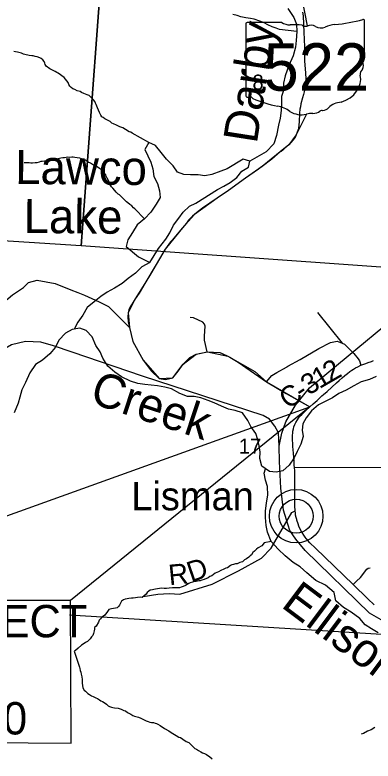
# Model space of a CAD drawing. Extents: x 0 to 82.7, y -0.2 to 22.
# Drawn here: x 6.593 to 7.589, y 16.831 to 18.905 of the extents above; entities that cross this region are included whole.
import ezdxf

# ---------------------------------------------------------------- set-up
doc = ezdxf.new("R2010")
doc.units = 0
for name, color, linetype in [('Default', 7, 'Continuous'), ('GM_X_County_Road', 7, 'Continuous'), ('GM_X_County_Road_Text', 7, 'Continuous'), ('GM_X_Minor_Lake', 7, 'Continuous'), ('GM_X_Minor_Lake_Text', 7, 'Continuous'), ('GM_X_Minor_River', 7, 'Continuous'), ('GM_X_Minor_River_Text', 7, 'Continuous'), ('GM_X_Rail_Line', 7, 'Continuous'), ('GM_X_Section', 7, 'Continuous'), ('GM_X_Section_Text', 7, 'Continuous'), ('GM_X_State_Location', 7, 'Continuous'), ('GM_X_State_Route', 7, 'Continuous'), ('GM_X_State_Shield', 7, 'Continuous'), ('GM_X_Township_Road', 7, 'Continuous'), ('GM_X_Unincorporated', 7, 'Continuous'), ('GM_X_Unincorporated_Location', 7, 'Continuous'), ('GM_X_Unincorporated_Text', 7, 'Continuous'), ('SH_Data', 7, 'Continuous'), ('SH_Text', 7, 'Continuous')]:
    doc.layers.add(name, color=color, linetype=linetype)

msp = doc.modelspace()

# ---------------------------------------------------------------- linework, layer by layer
at = {"layer": 'Default'}
msp.add_lwpolyline([(5.916, 17.2773), (5.9127, 16.8876), (6.7496, 16.8806), (6.7482, 17.2774)], dxfattribs=at)
at = {"layer": 'GM_X_County_Road'}
for points in [[(6.2254, 17.8971), (6.228, 17.8985), (6.3326, 17.9376), (6.3894, 17.9596), (6.4281, 17.9767), (6.4614, 17.9881), (6.4811, 17.9953), (6.491, 17.9995), (6.5004, 18.0158), (6.5137, 18.0488), (6.5251, 18.0704), (6.544, 18.0924), (6.5868, 18.1273), (6.6168, 18.1478), (6.6312, 18.1611), (6.655, 18.1676), (6.7047, 18.1592), (6.7488, 18.1415), (6.7681, 18.1337)], [(6.7681, 18.1337), (6.7865, 18.1263), (6.8275, 18.1081), (6.8532, 18.0944), (6.9114, 18.036)], [(7.3477, 17.9266), (7.3486, 17.9271), (7.3522, 17.9291), (7.3858, 17.9477), (7.438, 17.9776), (7.4703, 17.995), (7.4889, 17.9987), (7.503, 17.9926), (7.5088, 17.99), (7.5349, 17.9639), (7.5474, 17.949), (7.5511, 17.944), (7.5543, 17.9314)], [(7.2923, 17.8858), (7.3074, 17.903), (7.3211, 17.9117), (7.3477, 17.9266)], [(6.9494, 17.2887), (6.9909, 17.2954), (7.0224, 17.2973), (7.0515, 17.295), (7.1414, 17.3231), (7.2149, 17.36), (7.2785, 17.3953), (7.3058, 17.4233), (7.363, 17.522), (7.3722, 17.5271)]]:
    msp.add_lwpolyline(points, dxfattribs=at)
at = {"layer": 'GM_X_Minor_Lake'}
for points in [[(7.0958, 18.3823), (7.1566, 18.4199), (7.1741, 18.429), (7.1916, 18.4395), (7.2098, 18.4539), (7.2243, 18.4712), (7.2425, 18.4818), (7.2464, 18.4992), (7.2275, 18.5046), (7.1834, 18.4775), (7.1652, 18.4708), (7.1402, 18.4618), (7.1212, 18.4581), (7.1023, 18.4612), (7.0811, 18.4613), (7.0629, 18.4621), (7.0455, 18.4683), (7.0327, 18.4858), (7.0146, 18.5041), (6.9996, 18.5232), (6.9838, 18.5422), (6.9656, 18.5506), (6.9542, 18.5317), (6.9624, 18.5135), (6.9707, 18.496), (6.9766, 18.4777), (6.9796, 18.4564), (6.9893, 18.4367), (6.9953, 18.4161), (6.9974, 18.3979), (6.986, 18.379), (6.9707, 18.357), (6.9532, 18.3389), (6.9334, 18.3215), (6.9204, 18.3003), (6.9067, 18.2799), (6.9021, 18.2617), (6.9369, 18.2329), (6.9685, 18.2174)], [(6.9685, 18.2174), (6.98, 18.2363), (6.9922, 18.256), (7.0128, 18.2824), (7.0242, 18.2999), (7.0342, 18.3211), (7.0487, 18.34), (7.0609, 18.3574), (7.0784, 18.374), (7.0958, 18.3823)]]:
    msp.add_lwpolyline(points, dxfattribs=at)
at = {"layer": 'GM_X_Minor_River'}
for points in [[(7.3515, 18.9232), (7.3687, 18.8981), (7.3755, 18.8798), (7.3772, 18.8593), (7.3751, 18.8346), (7.3735, 18.8157), (7.3669, 18.7918), (7.3546, 18.7645), (7.3445, 18.7361), (7.3398, 18.7156), (7.3393, 18.6958), (7.3339, 18.6784), (7.3341, 18.6583), (7.3336, 18.6401), (7.3305, 18.618), (7.3262, 18.5991), (7.3203, 18.5699), (7.3133, 18.5471), (7.2912, 18.5252), (7.2464, 18.4992)], [(7.3772, 18.8593), (7.329, 18.8651), (7.3191, 18.8685), (7.3084, 18.8727), (7.2963, 18.878), (7.2856, 18.8837), (7.2739, 18.8883), (7.2579, 18.8933), (7.2476, 18.8952), (7.2351, 18.8978), (7.2214, 18.9005), (7.2108, 18.9036), (7.199, 18.9066)], [(6.9656, 18.5506), (6.9192, 18.5765), (6.9155, 18.5795), (6.9105, 18.5807), (6.9004, 18.587), (6.8928, 18.5912), (6.8849, 18.594), (6.8807, 18.5963), (6.8758, 18.5987), (6.8672, 18.603), (6.8623, 18.6049), (6.8578, 18.6095), (6.8487, 18.6138), (6.8434, 18.6162), (6.8389, 18.6204), (6.8348, 18.6224), (6.8321, 18.6266), (6.8284, 18.6342), (6.8255, 18.6407), (6.8229, 18.6468), (6.8211, 18.6514), (6.8188, 18.6568), (6.817, 18.6606), (6.8151, 18.6648), (6.8118, 18.669), (6.8073, 18.6744), (6.8035, 18.6782), (6.7994, 18.6813), (6.7941, 18.6829), (6.7892, 18.6849), (6.7847, 18.6872), (6.7782, 18.6899), (6.7745, 18.6923), (6.7665, 18.6946), (6.7594, 18.6978), (6.7545, 18.6997), (6.7499, 18.7036), (6.7458, 18.7078), (6.7432, 18.712), (6.741, 18.7174), (6.7376, 18.7227), (6.7343, 18.727), (6.7298, 18.7312), (6.7238, 18.7362), (6.72, 18.7393), (6.7136, 18.7439), (6.7098, 18.7451), (6.7053, 18.7482), (6.7, 18.751), (6.6944, 18.7537), (6.6902, 18.756), (6.6804, 18.763), (6.6778, 18.7672), (6.676, 18.7714), (6.6742, 18.7764), (6.6712, 18.7802), (6.6659, 18.7841), (6.6621, 18.7864), (6.6553, 18.7891), (6.6497, 18.7903), (6.6444, 18.7916), (6.6402, 18.792), (6.633, 18.7925), (6.6288, 18.794), (6.6243, 18.7945), (6.6167, 18.7961), (6.6114, 18.7988), (6.6001, 18.8016), (6.5952, 18.8028), (6.5906, 18.8036)], [(6.9532, 18.3389), (6.9267, 18.3666), (6.9229, 18.3693), (6.9184, 18.3751), (6.9128, 18.3786), (6.9075, 18.3832), (6.9037, 18.3855), (6.8981, 18.3913), (6.8928, 18.3956), (6.8899, 18.4001), (6.8842, 18.4055), (6.8801, 18.4075), (6.8745, 18.4129), (6.8707, 18.4175), (6.8655, 18.424), (6.8617, 18.4271), (6.858, 18.4332), (6.8558, 18.439), (6.8532, 18.4447), (6.8495, 18.4516), (6.8473, 18.4573), (6.8462, 18.4611), (6.8417, 18.4669), (6.8395, 18.4707), (6.8342, 18.4749), (6.8282, 18.4788), (6.8191, 18.485), (6.812, 18.4874), (6.8029, 18.4932), (6.7965, 18.4959), (6.789, 18.5013), (6.7825, 18.5037), (6.7735, 18.5076), (6.7667, 18.5085), (6.7595, 18.5093), (6.7553, 18.5097), (6.7515, 18.5098), (6.7451, 18.5095), (6.7397, 18.5096), (6.7356, 18.5089), (6.7314, 18.5085), (6.7264, 18.5078), (6.7207, 18.5068), (6.7135, 18.505), (6.7082, 18.5039), (6.701, 18.5028), (6.6968, 18.5021), (6.6861, 18.5007), (6.6808, 18.4997), (6.6755, 18.4993), (6.6687, 18.4983), (6.6649, 18.4976), (6.6607, 18.4957), (6.6542, 18.4943), (6.6496, 18.494), (6.6421, 18.4933), (6.6379, 18.4934), (6.6326, 18.4938), (6.6265, 18.4939), (6.6193, 18.4944)], [(6.9685, 18.2174), (6.9458, 18.205), (6.9286, 18.1876), (6.9081, 18.1729), (6.8909, 18.1586), (6.8703, 18.1458), (6.8494, 18.1345), (6.8323, 18.1228), (6.8136, 18.1077), (6.7945, 18.0918), (6.7822, 18.071), (6.7684, 18.051), (6.7585, 18.0335), (6.758, 18.0315)], [(7.2724, 17.7071), (7.268, 17.7242), (7.2628, 17.7417), (7.2493, 17.7611), (7.2403, 17.7782), (7.2256, 17.7988), (7.2056, 17.8057), (7.1866, 17.8092), (7.167, 17.8177), (7.1473, 17.8269), (7.1299, 17.8331), (7.1099, 17.8408), (7.0913, 17.845), (7.0727, 17.8448), (7.0519, 17.8525), (7.0289, 17.8659), (7.0096, 17.8701), (6.9895, 17.874), (6.9721, 17.8764), (6.9546, 17.8776), (6.9353, 17.8811), (6.9149, 17.8873), (6.8895, 17.8996), (6.871, 17.9122), (6.8514, 17.929), (6.8379, 17.9515), (6.8301, 17.969), (6.8184, 17.9865), (6.8084, 18.0101), (6.791, 18.0277), (6.7733, 18.0342), (6.7528, 18.0305), (6.7337, 18.0211), (6.7154, 18.0015), (6.7062, 17.9822), (6.6905, 17.9629), (6.6695, 17.9455), (6.6509, 17.9339), (6.6344, 17.9104), (6.6225, 17.8839), (6.6121, 17.8634), (6.607, 17.8429), (6.6023, 17.8259), (6.5912, 17.7994)], [(7.5976, 17.9006), (7.5789, 17.8923), (7.5554, 17.8852), (7.5348, 17.8739), (7.5135, 17.8623), (7.4933, 17.8529), (7.4762, 17.8412), (7.4366, 17.8216), (7.4176, 17.805), (7.4026, 17.7857), (7.3934, 17.7683), (7.3918, 17.7509), (7.3947, 17.7334), (7.3877, 17.7118), (7.3781, 17.6917), (7.3693, 17.6739), (7.3555, 17.6539), (7.3379, 17.6376), (7.3193, 17.6343), (7.3004, 17.6363), (7.2796, 17.6512), (7.2737, 17.6721), (7.2746, 17.69), (7.2724, 17.7071)], [(7.6027, 17.1871), (7.5845, 17.1989), (7.5668, 17.2097), (7.5514, 17.2272), (7.528, 17.2452), (7.5061, 17.2582), (7.4853, 17.2765), (7.4802, 17.3001), (7.456, 17.3203), (7.4296, 17.3326), (7.4043, 17.3544), (7.3862, 17.3708), (7.3666, 17.3831), (7.3439, 17.4018), (7.3247, 17.4197), (7.3055, 17.4415), (7.2955, 17.467), (7.2918, 17.4856), (7.2897, 17.5084), (7.2898, 17.5262), (7.2922, 17.5486), (7.2965, 17.5706), (7.2948, 17.5942), (7.2896, 17.612), (7.2856, 17.6314), (7.2898, 17.6439)], [(7.3055, 17.4415), (7.2862, 17.4377), (7.2793, 17.4298), (7.269, 17.4235), (7.2648, 17.4201), (7.2594, 17.4145), (7.2548, 17.4108), (7.2509, 17.4047), (7.2467, 17.4017), (7.2429, 17.398), (7.2368, 17.3931), (7.2314, 17.3901), (7.2253, 17.3853), (7.2188, 17.3827), (7.2112, 17.3798), (7.2066, 17.3791), (7.2009, 17.3776), (7.1964, 17.3769), (7.1925, 17.3751), (7.1841, 17.3687), (7.1796, 17.3672), (7.1738, 17.3647), (7.1658, 17.361), (7.1586, 17.3572), (7.1494, 17.3532), (7.1448, 17.3498), (7.1406, 17.3461), (7.1353, 17.3446), (7.1303, 17.3409), (7.1196, 17.3357), (7.1128, 17.3339), (7.1082, 17.332), (7.104, 17.3317), (7.0972, 17.3307), (7.093, 17.33), (7.0869, 17.3285), (7.0804, 17.3267), (7.0762, 17.3245), (7.0671, 17.3193), (7.061, 17.3163), (7.0553, 17.3148), (7.0503, 17.313), (7.0465, 17.3131), (7.0416, 17.3124), (7.0355, 17.3124), (7.0313, 17.3125), (7.0215, 17.3115), (7.0146, 17.3108), (7.0078, 17.3109), (6.9995, 17.3114), (6.9953, 17.3107), (6.9896, 17.3096), (6.9843, 17.3089), (6.9793, 17.3078), (6.9755, 17.3075), (6.9694, 17.3057), (6.9652, 17.3038), (6.961, 17.2997), (6.9583, 17.2955), (6.9537, 17.2914), (6.9468, 17.2862), (6.9415, 17.2863), (6.9335, 17.286), (6.9286, 17.2853), (6.9217, 17.2842), (6.9176, 17.2839), (6.9103, 17.2828), (6.9054, 17.2818), (6.9001, 17.2807), (6.8951, 17.2789), (6.8898, 17.2755), (6.8878, 17.2717), (6.8855, 17.268), (6.8836, 17.2642), (6.8813, 17.2604), (6.877, 17.257), (6.8732, 17.256), (6.8675, 17.2553), (6.8618, 17.2538), (6.8546, 17.252), (6.8504, 17.2471), (6.8434, 17.2369), (6.8342, 17.2306), (6.8315, 17.2268), (6.8277, 17.2231), (6.8254, 17.217), (6.8195, 17.2065), (6.8146, 17.202), (6.8149, 17.1978), (6.8133, 17.1929), (6.8113, 17.1853), (6.8094, 17.1804), (6.8059, 17.1762), (6.8028, 17.1706), (6.7948, 17.1631), (6.7898, 17.1609), (6.7833, 17.1564), (6.7783, 17.1534), (6.7695, 17.1452), (6.7619, 17.1388), (6.758, 17.1369)], [(6.758, 17.1369), (6.7731, 17.0923), (6.7738, 17.0885), (6.7749, 17.0824), (6.776, 17.0782), (6.7774, 17.0725), (6.7792, 17.0649), (6.7806, 17.0576), (6.7806, 17.0523), (6.7805, 17.0474), (6.7808, 17.0409), (6.7823, 17.0344), (6.786, 17.0283), (6.7898, 17.0252), (6.7958, 17.0191), (6.8007, 17.016), (6.8059, 17.0125), (6.8112, 17.0105), (6.8184, 17.0066), (6.8229, 17.0051), (6.8282, 17.0016), (6.8323, 16.9989), (6.8365, 16.9969), (6.841, 16.9938), (6.8474, 16.9892), (6.8527, 16.9849), (6.8564, 16.9826), (6.8613, 16.981), (6.8651, 16.9795), (6.8697, 16.979), (6.8803, 16.9781), (6.8882, 16.9757), (6.8958, 16.9719), (6.9007, 16.9706), (6.9059, 16.9664), (6.9157, 16.9613), (6.9214, 16.9579), (6.9255, 16.9563), (6.9331, 16.9539), (6.9369, 16.9531), (6.9429, 16.95), (6.9471, 16.9488), (6.9524, 16.9453), (6.958, 16.9433), (6.9637, 16.941), (6.9686, 16.939), (6.9728, 16.9382), (6.9788, 16.9381), (6.9826, 16.9366), (6.9868, 16.9358), (6.9909, 16.9338), (6.9966, 16.9303), (7.0086, 16.9218), (7.0211, 16.9152), (7.0271, 16.9109), (7.0369, 16.9051), (7.0414, 16.9024), (7.0489, 16.8977), (7.0531, 16.8962), (7.0595, 16.8915), (7.0689, 16.8857), (7.0768, 16.8822), (7.0813, 16.8783), (7.0933, 16.866), (7.0979, 16.8641), (7.1039, 16.8606), (7.1099, 16.8567), (7.1148, 16.854), (7.1197, 16.8524), (7.1254, 16.8489), (7.1295, 16.8462), (7.1341, 16.8439), (7.1416, 16.8373)], [(7.5936, 16.9245), (7.5837, 16.9181), (7.5727, 16.914), (7.5617, 16.9072), (7.5552, 16.9058)]]:
    msp.add_lwpolyline(points, dxfattribs=at)
at = {"layer": 'GM_X_Rail_Line'}
for points in [[(7.3273, 17.7066), (7.335, 17.743), (7.346, 17.7746), (7.3734, 17.8206), (7.4119, 17.8691), (7.7503, 18.1483), (7.8617, 18.235), (8.0519, 18.4025), (8.1745, 18.5326), (8.3001, 18.66), (8.3381, 18.7253), (8.3827, 18.8457), (8.5197, 19.18), (8.5273, 19.1937), (8.5384, 19.2118)], [(7.3273, 17.7066), (7.3259, 17.7432), (7.3159, 17.7619), (7.3005, 17.7817), (7.283, 17.7916), (6.9482, 17.9012), (6.7526, 17.9674), (6.7006, 17.9857), (6.665, 17.9956), (6.6225, 17.9973), (6.584, 17.9881), (6.5551, 17.9713), (6.5062, 17.9483), (6.3111, 17.8299), (6.3099, 17.8288), (5.7871, 17.5166), (5.7628, 17.4965), (5.7274, 17.4651), (5.5819, 17.3372), (5.4314, 17.2126), (5.3996, 17.1841), (5.3803, 17.1691), (5.3466, 17.155)], [(7.6107, 17.2233), (7.5791, 17.2424), (7.3997, 17.4162), (7.374, 17.4476), (7.3571, 17.4717), (7.3482, 17.5013), (7.3395, 17.5282), (7.3325, 17.5893), (7.3283, 17.6641), (7.3273, 17.7066)]]:
    msp.add_lwpolyline(points, dxfattribs=at)
at = {"layer": 'GM_X_Section'}
for points in [[(5.8471, 19.3468), (6.8524, 19.275), (6.7772, 18.2637), (5.7783, 18.3279)], [(6.8524, 19.275), (7.8698, 19.2002), (7.7927, 18.1915), (6.7772, 18.2637)]]:
    msp.add_lwpolyline(points, close=True, dxfattribs=at)
msp.add_lwpolyline([(6.7452, 17.2376), (7.7171, 17.1775), (7.6497, 16.1665), (6.6409, 16.2254), (6.6789, 16.7875)], dxfattribs=at)
at = {"layer": 'GM_X_State_Route'}
for points in [[(7.3927, 18.9136), (7.394, 18.903), (7.3946, 18.8964), (7.3954, 18.886), (7.3957, 18.8762), (7.3965, 18.8605), (7.3975, 18.834), (7.3979, 18.8197), (7.3981, 18.7779), (7.4008, 18.7433), (7.4017, 18.7281), (7.4012, 18.7183), (7.3998, 18.704), (7.3973, 18.6918), (7.3952, 18.6841), (7.3925, 18.6748), (7.3883, 18.658), (7.3865, 18.6502), (7.3855, 18.6433), (7.3842, 18.6323), (7.383, 18.6087), (7.3811, 18.5908), (7.3801, 18.5866), (7.3778, 18.5791), (7.3753, 18.5725), (7.373, 18.5676), (7.3728, 18.5672), (7.3691, 18.5618), (7.3659, 18.5575), (7.3541, 18.5443), (7.3483, 18.539), (7.3437, 18.5347), (7.3385, 18.5308), (7.3328, 18.5259), (7.3309, 18.5245), (7.3071, 18.5044), (7.2803, 18.484), (7.2786, 18.4829), (7.2701, 18.4766), (7.2343, 18.4513), (7.2175, 18.4396), (7.1864, 18.4175), (7.1557, 18.3958), (7.1146, 18.3679), (7.1021, 18.3587), (7.0925, 18.3509), (7.0869, 18.3459), (7.082, 18.341), (7.0761, 18.3345), (7.0698, 18.3265), (7.0594, 18.3139), (7.0302, 18.2795), (7.0256, 18.2745), (7.0161, 18.2616), (7.0112, 18.2539), (7.0042, 18.2427), (6.986, 18.2118), (6.9702, 18.1847), (6.9544, 18.1588), (6.9389, 18.1321), (6.9272, 18.1161), (6.9187, 18.1026), (6.9139, 18.0942), (6.9097, 18.0853), (6.9079, 18.0771), (6.9071, 18.066), (6.9079, 18.0516), (6.9114, 18.036), (6.9213, 17.9979), (6.9495, 17.9457), (6.9727, 17.9151), (6.9945, 17.8951), (7.0122, 17.8923), (7.032, 17.8967), (7.0473, 17.9155), (7.0608, 17.9343), (7.0795, 17.9527), (7.097, 17.962), (7.1277, 17.9687), (7.1285, 17.9689), (7.1626, 17.967), (7.1688, 17.9642), (7.1847, 17.957)], [(7.1847, 17.957), (7.1909, 17.9542), (7.2138, 17.9403), (7.2923, 17.8858), (7.413, 17.816)], [(7.413, 17.816), (7.4224, 17.8244), (7.433, 17.8339), (7.4415, 17.8419), (7.4463, 17.846), (7.4513, 17.8505), (7.4606, 17.8588), (7.4736, 17.8703), (7.4869, 17.8822), (7.4946, 17.8889), (7.5028, 17.8963), (7.5106, 17.903), (7.5174, 17.9087), (7.524, 17.9139), (7.5295, 17.9175), (7.5347, 17.921), (7.5401, 17.9242), (7.5459, 17.9272), (7.5543, 17.9314), (7.5625, 17.9347), (7.5681, 17.9367), (7.5752, 17.9392), (7.5839, 17.9421), (7.5901, 17.9444)], [(7.3722, 17.5271), (7.3711, 17.5403), (7.3711, 17.549), (7.3713, 17.5551), (7.3712, 17.5709), (7.3712, 17.5875), (7.3712, 17.6027), (7.3711, 17.6174), (7.371, 17.6258), (7.3708, 17.6369), (7.37, 17.6479), (7.3698, 17.6525), (7.3689, 17.6651), (7.3681, 17.6759), (7.3674, 17.6864), (7.3666, 17.6973), (7.3661, 17.7051), (7.3655, 17.7146), (7.365, 17.722), (7.3647, 17.7288), (7.3648, 17.737), (7.3652, 17.7426), (7.366, 17.7483), (7.3673, 17.7545), (7.3687, 17.7603), (7.371, 17.7664), (7.3738, 17.7727), (7.3782, 17.78), (7.381, 17.7842), (7.3855, 17.7896), (7.3904, 17.7949), (7.3958, 17.8), (7.4021, 17.8059), (7.413, 17.816)], [(7.3765, 17.5022), (7.3749, 17.5085), (7.3735, 17.5151), (7.3728, 17.5203), (7.3722, 17.5271)], [(7.5921, 17.265), (7.5737, 17.2821), (7.533, 17.3223), (7.4282, 17.4229), (7.4132, 17.4382), (7.4028, 17.4497), (7.4001, 17.4531), (7.3962, 17.4589), (7.3912, 17.4666), (7.3891, 17.4704), (7.3826, 17.4842), (7.3801, 17.4908), (7.3768, 17.501), (7.3765, 17.5022)]]:
    msp.add_lwpolyline(points, dxfattribs=at)
at = {"layer": 'GM_X_State_Shield'}
for p, q in [((7.235, 18.8808), (7.235, 18.6807)), ((7.3348, 18.8842), (7.2383, 18.8842)), ((7.5646, 18.7845), (7.5646, 18.8892)), ((7.5646, 18.7845), (7.5646, 18.7845))]:
    msp.add_line(p, q, dxfattribs=at)
for centre, major_axis, start_param, end_param in [((7.2388, 18.8812), (0.00382, 0), 1.712693, 3.28349), ((7.3578, 18.9075), (0.037, 0), 4.042523, 4.731795), ((7.37, 18.7719), (0.133, 0), 1.404758, 1.657858), ((7.4159, 18.8591), (0.0222, 0), 0.950623, 2.079405), ((7.4918, 18.8231), (0.0703, 0), 1.699011, 2.107814), ((7.4472, 19.1571), (0.3495, 0), 4.814394, 5.042369), ((7.5609, 18.8896), (0.00367, 0), 6.141152, 7.989035), ((7.4002, 18.8823), (0.0107, 0), 3.836095, 5.185415), ((7.4446, 18.8909), (0.0267, 0), 4.081561, 5.145723), ((7.5638, 18.7768), (0.00568, 0), 1.883978, 3.671073), ((7.5276, 18.7636), (0.0341, 0), 5.934695, 6.695948), ((7.5607, 18.7841), (0.00393, 0), 5.05454, 6.418171), ((7.5777, 18.7407), (0.0248, 0), 2.387724, 3.262537), ((7.4668, 18.7274), (0.0874, 0), 5.101752, 6.440018), ((7.2388, 18.6802), (0.00385, 0), 3.00124, 4.508301), ((7.2394, 18.7007), (0.0294, 0), 4.665946, 4.897461), ((7.2454, 18.6691), (0.0106, 0), 0.519207, 1.627899), ((7.3792, 18.8489), (0.2524, 0), 4.195997, 4.488961), ((7.304, 18.5908), (0.079, 0), 0.823519, 1.323587), ((7.5036, 18.6245), (0.0479, 0), 1.647645, 2.488434), ((7.3894, 18.6681), (0.0501, 0), 4.026481, 4.996735), ((7.4184, 18.5989), (0.0412, 0), 1.495662, 1.94098), ((7.422, 18.6532), (0.0267, 0), 4.691044, 5.507374), ((7.4462, 18.6338), (0.00752, 0), 1.147584, 2.315152), ((7.443, 18.6613), (0.0282, 0), 4.937069, 5.64225)]:
    msp.add_ellipse(centre, major_axis=major_axis, ratio=0.8, start_param=start_param, end_param=end_param, dxfattribs=at)
at = {"layer": 'GM_X_Township_Road'}
for p, q in [((7.4342, 18.0782), (7.503, 17.9926)), ((7.37, 17.6479), (7.6608, 17.6474))]:
    msp.add_line(p, q, dxfattribs=at)
for points in [[(7.1277, 17.9687), (7.1201, 18.0014), (7.1199, 18.0126), (7.1224, 18.0405), (7.1201, 18.0455), (7.1153, 18.0511), (7.0897, 18.063), (7.0805, 18.0643)], [(7.533, 17.3223), (7.5425, 17.3312), (7.5534, 17.3418), (7.5712, 17.3645), (7.5749, 17.367), (7.5802, 17.3681)]]:
    msp.add_lwpolyline(points, dxfattribs=at)
at = {"layer": 'GM_X_Unincorporated'}
for radius in [0.0744, 0.0472]:
    msp.add_circle((7.375, 17.5118), radius, dxfattribs=at)
at = {"layer": 'GM_X_Unincorporated_Location'}
msp.add_line((7.375, 17.5118), (7.375, 17.5118), dxfattribs=at)
at = {"layer": 'SH_Data'}
msp.add_lwpolyline([(5.9155, 17.2774), (7.413, 17.816), (6.7482, 17.2774)], close=True, dxfattribs=at)
at = {"layer": 'SH_Text'}
for p, q in [((7.392, 18.9474), (7.4051, 18.8747)), ((7.4035, 18.6297), (7.3753, 18.5725)), ((7.3753, 18.5725), (7.3541, 18.5443)), ((7.3753, 18.5725), (7.3753, 18.5725)), ((7.3541, 18.5443), (7.3309, 18.5245)), ((7.3309, 18.5245), (7.2803, 18.484)), ((7.2803, 18.484), (7.2343, 18.4513)), ((7.2343, 18.4513), (7.1864, 18.4175)), ((7.1864, 18.4175), (7.1557, 18.3958)), ((7.1557, 18.3958), (7.0925, 18.3509)), ((7.0925, 18.3509), (7.0594, 18.3139)), ((7.0925, 18.3509), (7.0925, 18.3509)), ((7.0594, 18.3139), (7.0112, 18.2539)), ((7.0112, 18.2539), (6.986, 18.2118)), ((6.986, 18.2118), (6.9544, 18.1588)), ((6.9544, 18.1588), (6.9272, 18.1161)), ((6.9272, 18.1161), (6.9079, 18.0771)), ((6.9079, 18.0771), (6.9114, 18.036)), ((6.9114, 18.036), (6.9213, 17.9979)), ((6.9213, 17.9979), (6.9495, 17.9457)), ((7.097, 17.962), (7.1285, 17.9689)), ((7.1285, 17.9689), (7.1847, 17.957)), ((6.9495, 17.9457), (6.9945, 17.8951)), ((7.0608, 17.9343), (7.097, 17.962)), ((7.1847, 17.957), (7.2596, 17.9139)), ((7.032, 17.8967), (7.0608, 17.9343)), ((7.2596, 17.9139), (7.2923, 17.8858)), ((6.9945, 17.8951), (7.032, 17.8967)), ((7.2923, 17.8858), (7.3475, 17.853)), ((7.3475, 17.853), (7.413, 17.816))]:
    msp.add_line(p, q, dxfattribs=at)

# ---------------------------------------------------------------- texts
at = {"layer": 'Default'}
for s, p in [('END PROJECT', (5.945, 17.175)), ('S.L.M. 8.290', (5.945, 16.905))]:
    msp.add_text(s, height=0.09, dxfattribs=at).set_placement(p)
at = {"layer": 'GM_X_County_Road_Text'}
for s, rotation, p in [('2', 29.7271, (7.4694, 17.8822)), ('1', 30.1118, (7.4393, 17.8647)), ('3', 31.4841, (7.4097, 17.8466)), ('C', 35.3335, (7.3529, 17.8075)), ('-', 32.7981, (7.3904, 17.8341)), ('D', 18.8699, (7.0829, 17.3274)), ('R', 5.5762, (7.0227, 17.3198))]:
    msp.add_text(s, height=0.0568, rotation=rotation, dxfattribs=at).set_placement(p)
at = {"layer": 'GM_X_Minor_Lake_Text'}
for s, rotation, p in [('Lawco', 359.4987, (6.5937, 18.4357)), ('Lake', 359.4988, (6.6171, 18.2993))]:
    msp.add_text(s, height=0.0947, rotation=rotation, dxfattribs=at).set_placement(p)
at = {"layer": 'GM_X_Minor_River_Text'}
for s, height, rotation, p in [('Darby', 0.09469, 81.1077, (7.2654, 18.5455)), ('Creek', 0.09469, 341.8119, (6.7977, 17.8282)), ('Ellisonville', 0.094688, 323.0648, (7.33, 17.2613))]:
    msp.add_text(s, height=height, rotation=rotation, dxfattribs=at).set_placement(p)
at = {"layer": 'GM_X_Section_Text'}
for s, height, p in [('8', 0.0419, (7.2534, 18.6976)), ('17', 0.04186, (7.2155, 17.6856))]:
    msp.add_text(s, height=height, rotation=0, dxfattribs=at).set_placement(p)
at = {"layer": 'GM_X_State_Location'}
msp.add_text('522', height=0.000189, rotation=0, dxfattribs=at).set_placement((7.3292, 18.7537))
for s in ['s', 'r']:
    msp.add_text(s, height=0.000189, dxfattribs=at).set_placement((7.3961, 18.7674))
at = {"layer": 'GM_X_State_Shield'}
msp.add_text('522', height=0.13184, dxfattribs=at).set_placement((7.284, 18.6948))
at = {"layer": 'GM_X_Unincorporated_Text'}
msp.add_text('Lisman', height=0.07898, rotation=0, dxfattribs=at).set_placement((6.9167, 17.5283))

doc.saveas('drawing.dxf')
